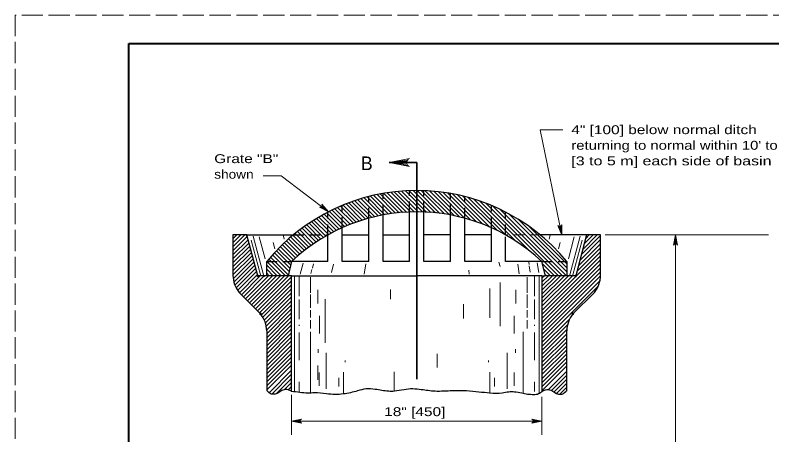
# Model space of a CAD drawing. Extents: x 1302.9 to 1336.9, y 688.5 to 710.5.
# Drawn here: x 1302.88 to 1316.19, y 703.12 to 710.5 of the extents above; entities that cross this region are included whole.
import ezdxf
from ezdxf.enums import TextEntityAlignment as Align

# ---------------------------------------------------------------- set-up
doc = ezdxf.new("R2010")
doc.units = 0
doc.header["$LTSCALE"] = 0.062
doc.header["$PDMODE"] = 32
doc.header["$PDSIZE"] = 0.031
doc.linetypes.add('LONG_DASHED', pattern=[7.5, 6, -1.5])
doc.linetypes.add('MEDIUM_DASHED', pattern=[4.5, 3, -1.5])
doc.layers.add('1', color=7, linetype='Continuous', lineweight=13)

msp = doc.modelspace()

# ---------------------------------------------------------------- linework, layer by layer
at = {"layer": '1', "lineweight": 25}
for p, q in [((1304.8765, 710.00158), (1336.3765, 710.00158)), ((1309.348, 706.16867), (1309.348, 706.98783)), ((1309.81658, 706.16867), (1309.81658, 707.04075)), ((1310.06642, 706.16867), (1310.06642, 707.04075)), ((1310.535, 706.16867), (1310.535, 706.98783)), ((1309.09817, 706.16867), (1309.09817, 706.93033)), ((1310.78483, 706.16867), (1310.78483, 706.93033)), ((1308.62958, 706.16867), (1308.62958, 706.76283)), ((1311.25342, 706.16867), (1311.25342, 706.76283)), ((1306.95333, 706.63708), (1306.70858, 706.63708)), ((1306.70858, 706.63708), (1306.70858, 705.92617)), ((1307.14592, 705.91875), (1306.95333, 706.63708)), ((1306.95333, 706.63708), (1307.76892, 706.63708)), ((1308.37975, 706.16867), (1308.37975, 706.63758)), ((1308.62958, 706.63708), (1309.09817, 706.63708)), ((1309.348, 706.63708), (1309.81658, 706.63708)), ((1310.535, 706.63708), (1310.06642, 706.63708)), ((1311.25342, 706.63708), (1310.78483, 706.63708)), ((1311.50325, 706.16867), (1311.50325, 706.60317)), ((1312.92967, 706.63708), (1312.11408, 706.63708)), ((1313.17442, 706.63708), (1312.92967, 706.63708)), ((1313.17442, 705.92617), (1313.17442, 706.63708)), ((1307.30208, 705.91875), (1307.30208, 706.16867)), ((1308.37975, 706.16867), (1307.73933, 706.16867)), ((1309.09817, 706.16867), (1308.62958, 706.16867)), ((1309.81658, 706.16867), (1309.348, 706.16867)), ((1310.535, 706.16867), (1310.06642, 706.16867)), ((1311.25342, 706.16867), (1310.78483, 706.16867)), ((1312.14367, 706.16867), (1311.50325, 706.16867)), ((1312.58092, 706.16867), (1312.58092, 705.91875)), ((1307.30208, 705.91875), (1307.14592, 705.91875)), ((1307.73933, 705.91875), (1307.67692, 705.91875)), ((1307.73933, 705.91875), (1309.9415, 705.91875)), ((1307.73933, 703.90008), (1307.73933, 705.91875)), ((1312.14367, 705.91875), (1309.9415, 705.91875)), ((1312.14367, 705.91875), (1312.14367, 703.8845)), ((1306.81608, 705.62758), (1307.1945, 705.24925)), ((1312.6885, 705.24925), (1313.06692, 705.62758)), ((1307.30192, 704.95067), (1307.302, 703.9005)), ((1312.58092, 703.88883), (1312.58108, 704.95067))]:
    msp.add_line(p, q, dxfattribs=at)
at = {"layer": '1'}
for p, q in [((1309.77792, 707.95417), (1309.45742, 707.90933)), ((1309.767, 707.932), (1309.45742, 707.90933)), ((1309.76375, 707.90933), (1309.45742, 707.90933)), ((1309.76942, 707.8805), (1309.45742, 707.90933)), ((1309.78167, 707.85975), (1309.45742, 707.90933)), ((1309.82958, 707.04075), (1309.48342, 707.38683)), ((1309.89842, 707.04258), (1309.54642, 707.3945)), ((1309.96892, 707.04275), (1309.60983, 707.40175)), ((1310.04117, 707.04108), (1309.67533, 707.407)), ((1310.11475, 707.03833), (1309.74108, 707.41183)), ((1310.19058, 707.03317), (1309.80875, 707.41492)), ((1310.26842, 707.026), (1309.87733, 707.41692)), ((1310.34808, 707.017), (1309.94725, 707.41767)), ((1310.43017, 707.00558), (1310.01917, 707.4165)), ((1310.51542, 706.991), (1310.09192, 707.41442)), ((1310.60342, 706.97367), (1310.16692, 707.41008)), ((1310.69467, 706.95308), (1310.24367, 707.404)), ((1310.78958, 706.92875), (1310.32192, 707.3965)), ((1310.88925, 706.89992), (1310.40275, 707.38625)), ((1309.20583, 706.95767), (1308.90658, 707.25692)), ((1309.26392, 706.97025), (1308.96075, 707.2735)), ((1309.32225, 706.98267), (1309.01533, 707.2895)), ((1309.382, 706.9935), (1309.07092, 707.30458)), ((1309.44242, 707.00383), (1309.12725, 707.319)), ((1309.50408, 707.01283), (1309.18442, 707.3325)), ((1309.56675, 707.02083), (1309.24233, 707.34525)), ((1309.6305, 707.02775), (1309.30133, 707.35683)), ((1309.69567, 707.03325), (1309.361, 707.36792)), ((1309.76158, 707.03808), (1309.42192, 707.37767)), ((1310.99433, 706.8655), (1310.48608, 707.37367)), ((1311.10633, 706.82417), (1310.5715, 707.35883)), ((1311.22717, 706.774), (1310.65967, 707.3415)), ((1311.35942, 706.7125), (1310.75167, 707.32008)), ((1311.50708, 706.63533), (1310.84742, 707.29508)), ((1311.68542, 706.52775), (1310.94725, 707.26583)), ((1308.24983, 707.12417), (1308.39133, 707.04583)), ((1308.26083, 707.12975), (1308.39133, 707.04583)), ((1308.26892, 707.13783), (1308.39133, 707.04583)), ((1308.27533, 707.15108), (1308.39133, 707.04583)), ((1308.27667, 707.16308), (1308.39133, 707.04583)), ((1308.82617, 706.84258), (1308.54858, 707.12017)), ((1308.87775, 706.86175), (1308.59742, 707.14208)), ((1308.93083, 706.87933), (1308.6475, 707.16258)), ((1308.98383, 706.897), (1308.69767, 707.18308)), ((1309.0385, 706.913), (1308.74917, 707.20242)), ((1309.09317, 706.929), (1308.80067, 707.22133)), ((1309.14942, 706.94333), (1308.85342, 707.23933)), ((1311.93717, 706.34675), (1311.05225, 707.23158)), ((1312.43583, 705.91875), (1311.16333, 707.19125)), ((1312.50658, 705.91875), (1311.282, 707.14308)), ((1308.577, 706.73842), (1308.312, 707.00333)), ((1308.62558, 706.7605), (1308.35808, 707.028)), ((1308.67442, 706.78225), (1308.40475, 707.05208)), ((1308.7245, 706.80292), (1308.45208, 707.07525)), ((1308.77467, 706.8235), (1308.49975, 707.09825)), ((1312.57717, 705.91875), (1311.41067, 707.08517)), ((1312.58092, 705.98575), (1311.55392, 707.01267)), ((1308.34467, 706.61742), (1308.09008, 706.87192)), ((1308.38992, 706.64275), (1308.13358, 706.89917)), ((1308.43583, 706.66758), (1308.177, 706.92633)), ((1308.48217, 706.69183), (1308.22167, 706.95233)), ((1308.52942, 706.71533), (1308.26642, 706.97825)), ((1312.58092, 706.05633), (1311.71908, 706.91817)), ((1308.12767, 706.481), (1307.88225, 706.72642)), ((1308.16958, 706.50975), (1307.92283, 706.75642)), ((1308.21275, 706.53725), (1307.96383, 706.78608)), ((1308.256, 706.56475), (1308.00542, 706.81525)), ((1308.30008, 706.59125), (1308.04767, 706.84367)), ((1312.58092, 706.12708), (1311.92717, 706.78075)), ((1312.44033, 706.78658), (1312.49383, 706.63383)), ((1312.45233, 706.78342), (1312.49383, 706.63383)), ((1312.46375, 706.784), (1312.49383, 706.63383)), ((1312.47733, 706.78958), (1312.49383, 706.63383)), ((1312.48625, 706.79767), (1312.49383, 706.63383)), ((1306.70858, 706.63567), (1306.71, 706.63708)), ((1306.70858, 706.42758), (1306.91817, 706.63708)), ((1306.70858, 706.49817), (1306.8475, 706.63708)), ((1306.70858, 706.56892), (1306.77683, 706.63708)), ((1306.70858, 706.35683), (1306.96083, 706.60917)), ((1306.96025, 706.61133), (1306.93442, 706.63708)), ((1307.24758, 705.93433), (1307.06483, 706.616)), ((1307.27483, 706.21675), (1307.17125, 706.60325)), ((1307.6115, 706.56558), (1307.59233, 706.63708)), ((1307.96442, 706.3615), (1307.72567, 706.60033)), ((1308.00433, 706.39225), (1307.76408, 706.6325)), ((1308.045, 706.42242), (1307.80275, 706.6645)), ((1308.08583, 706.45217), (1307.8425, 706.6955)), ((1312.2715, 706.56558), (1312.29067, 706.63708)), ((1312.60817, 706.21675), (1312.71175, 706.60325)), ((1312.63542, 705.93433), (1312.81817, 706.616)), ((1312.83558, 706.28592), (1313.17442, 706.62475)), ((1312.86142, 706.38242), (1313.11608, 706.63708)), ((1312.88725, 706.479), (1313.04542, 706.63708)), ((1312.91317, 706.57558), (1312.97475, 706.63708)), ((1312.92967, 706.63708), (1313.17442, 706.63708)), ((1313.17442, 706.63567), (1313.173, 706.63708)), ((1316.12867, 706.63708), (1313.25767, 706.63708)), ((1314.46908, 706.475), (1314.49383, 706.63708)), ((1314.4795, 706.48117), (1314.49383, 706.63708)), ((1314.49383, 706.48392), (1314.49383, 706.63708)), ((1314.50517, 706.48233), (1314.49383, 706.63708)), ((1314.51625, 706.47692), (1314.49383, 706.63708)), ((1314.49383, 700.27), (1314.49383, 706.63708)), ((1306.70858, 706.28625), (1306.97583, 706.55333)), ((1306.70858, 706.2155), (1306.99075, 706.49758)), ((1307.19508, 705.93508), (1307.03075, 706.54783)), ((1307.44708, 706.39033), (1307.41675, 706.5035)), ((1307.81, 706.23325), (1307.57742, 706.46583)), ((1307.84808, 706.26592), (1307.6135, 706.50042)), ((1307.88617, 706.2985), (1307.6505, 706.53408)), ((1307.92508, 706.33025), (1307.68783, 706.5675)), ((1312.43592, 706.39033), (1312.46625, 706.5035)), ((1312.688, 705.93508), (1312.85225, 706.54783)), ((1312.78375, 706.09275), (1313.17442, 706.48342)), ((1312.80967, 706.18942), (1313.17442, 706.55408)), ((1306.70858, 706.14492), (1307.00567, 706.44192)), ((1306.70858, 706.07417), (1307.02058, 706.38617)), ((1306.70858, 706.00358), (1307.0355, 706.3305)), ((1307.70992, 706.05075), (1307.43725, 706.32333)), ((1307.72408, 706.10725), (1307.4715, 706.35975)), ((1307.73808, 706.16383), (1307.50633, 706.39558)), ((1307.77308, 706.1995), (1307.54142, 706.43125)), ((1312.14367, 705.31142), (1313.17442, 706.342)), ((1312.75783, 705.99625), (1313.17442, 706.41275)), ((1306.70858, 705.93283), (1307.05042, 706.27475)), ((1306.71292, 705.8665), (1307.06542, 706.219)), ((1307.62975, 705.91875), (1307.33783, 706.21067)), ((1307.68167, 705.93758), (1307.37025, 706.24892)), ((1307.69575, 705.99417), (1307.40358, 706.28625)), ((1312.14367, 705.24075), (1313.17442, 706.27142)), ((1312.14367, 705.17008), (1313.17442, 706.20067)), ((1306.72433, 705.80725), (1307.08033, 706.16325)), ((1306.74158, 705.75392), (1307.09533, 706.1075)), ((1306.76417, 705.70575), (1307.11025, 706.05175)), ((1307.30208, 706.16867), (1307.30208, 705.91875)), ((1307.48842, 705.91875), (1307.30208, 706.10508)), ((1307.55908, 705.91875), (1307.30533, 706.1725)), ((1307.94542, 706.13883), (1307.89017, 705.94708)), ((1308.12483, 706.12967), (1308.105, 706.05483)), ((1308.47717, 706.12058), (1308.43892, 705.97692)), ((1309.04308, 706.13033), (1309.0175, 705.94708)), ((1311.38475, 706.16108), (1311.40583, 706.08192)), ((1311.72025, 706.12433), (1311.7455, 705.95242)), ((1311.91017, 706.15608), (1311.91592, 706.11717)), ((1311.9195, 706.09242), (1311.93542, 705.98417)), ((1312.06075, 706.14608), (1312.086, 705.97417)), ((1312.14367, 705.09942), (1313.17442, 706.13008)), ((1312.14367, 705.02875), (1313.17442, 706.05933)), ((1312.36517, 705.91875), (1312.153, 706.13083)), ((1306.79092, 705.66183), (1307.12517, 705.99608)), ((1306.82175, 705.62192), (1307.14017, 705.94033)), ((1306.857, 705.58667), (1307.18925, 705.91875)), ((1306.89242, 705.55133), (1307.25992, 705.91875)), ((1306.92775, 705.51592), (1307.33058, 705.91875)), ((1306.96308, 705.48058), (1307.40125, 705.91875)), ((1306.99842, 705.44533), (1307.472, 705.91875)), ((1307.03375, 705.41), (1307.54267, 705.91875)), ((1307.06908, 705.37458), (1307.61333, 705.91875)), ((1307.10442, 705.33925), (1307.684, 705.91875)), ((1307.25742, 705.89767), (1307.25175, 705.91875)), ((1307.41775, 705.91875), (1307.30208, 706.0345)), ((1307.34708, 705.91875), (1307.30208, 705.96375)), ((1307.73933, 705.903), (1307.72358, 705.91875)), ((1307.78883, 705.91875), (1307.78883, 703.87517)), ((1307.87325, 705.91875), (1307.87325, 705.56275)), ((1308.09817, 706.02908), (1308.07992, 705.95983)), ((1310.856, 706.01492), (1310.8655, 705.94708)), ((1312.00975, 705.91875), (1312.00975, 705.56275)), ((1312.09417, 705.91875), (1312.09417, 703.86108)), ((1312.14367, 704.95808), (1313.17442, 705.98875)), ((1312.20608, 705.91875), (1312.14367, 705.91875)), ((1312.14367, 705.38208), (1312.68042, 705.91875)), ((1312.14367, 705.45275), (1312.60975, 705.91875)), ((1312.14367, 705.52342), (1312.539, 705.91875)), ((1312.14367, 705.59408), (1312.46842, 705.91875)), ((1312.14367, 705.66475), (1312.39767, 705.91875)), ((1312.14367, 705.73542), (1312.32708, 705.91875)), ((1312.14367, 705.80608), (1312.25633, 705.91875)), ((1312.14367, 705.87675), (1312.18567, 705.91875)), ((1312.14367, 704.88742), (1313.17425, 705.91783)), ((1312.2945, 705.91875), (1312.17658, 706.03667)), ((1312.22383, 705.91875), (1312.20017, 705.94242)), ((1307.13975, 705.304), (1307.73933, 705.9035)), ((1307.17517, 705.26858), (1307.73933, 705.83283)), ((1308.06958, 705.89525), (1308.06958, 705.62117)), ((1311.4085, 705.80017), (1311.4085, 705.03308)), ((1311.88633, 705.89525), (1311.88633, 705.62117)), ((1312.14367, 704.81667), (1313.16567, 705.83858)), ((1307.20817, 705.231), (1307.73933, 705.76208)), ((1307.23642, 705.18858), (1307.73933, 705.6915)), ((1308.20092, 705.43125), (1308.20092, 705.67233)), ((1309.47825, 705.67967), (1309.47825, 705.509)), ((1311.22983, 705.17925), (1311.22983, 705.69792)), ((1311.68208, 705.43125), (1311.68208, 705.67233)), ((1312.14367, 704.746), (1313.13417, 705.7365)), ((1307.26075, 705.14225), (1307.73933, 705.62075)), ((1307.28008, 705.09092), (1307.73933, 705.55017)), ((1308.06958, 705.592), (1308.06958, 705.3545)), ((1311.88633, 705.592), (1311.88633, 705.3545)), ((1307.29392, 705.03408), (1307.73933, 705.47942)), ((1307.3015, 704.97092), (1307.73933, 705.40883)), ((1307.87325, 705.50067), (1307.87325, 705.15367)), ((1308.32858, 705.50792), (1308.32858, 704.74083)), ((1310.76283, 705.16825), (1310.76283, 705.42033)), ((1312.00975, 705.50067), (1312.00975, 705.15367)), ((1307.30192, 704.90067), (1307.73933, 705.33808)), ((1307.30192, 704.83008), (1307.73933, 705.2675)), ((1308.06958, 705.31442), (1308.06958, 705.1865)), ((1311.88633, 705.31442), (1311.88633, 705.1865)), ((1307.30192, 704.75933), (1307.73933, 705.19675)), ((1307.30192, 704.68875), (1307.73933, 705.12617)), ((1308.06958, 705.139), (1308.06958, 704.99292)), ((1308.23008, 704.9015), (1308.23008, 705.21567)), ((1311.65292, 704.9015), (1311.65292, 705.21567)), ((1311.88633, 705.139), (1311.88633, 704.99292)), ((1312.14367, 704.67533), (1312.63325, 705.16492)), ((1307.30192, 704.618), (1307.73933, 705.05542)), ((1307.30192, 704.54742), (1307.73933, 704.98475)), ((1307.87325, 705.05858), (1307.87325, 705.04033)), ((1312.00975, 705.05858), (1312.00975, 705.04033)), ((1312.14367, 704.60475), (1312.59317, 705.05417)), ((1307.302, 704.47667), (1307.73933, 704.91408)), ((1307.87325, 704.91983), (1307.87325, 704.434)), ((1308.06958, 704.93075), (1308.06958, 703.94083)), ((1311.81342, 704.93075), (1311.81342, 703.94083)), ((1312.00975, 704.91983), (1312.00975, 704.434)), ((1312.14367, 704.534), (1312.58208, 704.97242)), ((1312.14367, 704.46333), (1312.58108, 704.90075)), ((1307.302, 704.40608), (1307.73933, 704.84342)), ((1307.302, 704.33542), (1307.73933, 704.77275)), ((1312.14367, 704.39267), (1312.58108, 704.83008)), ((1312.14367, 704.322), (1312.58108, 704.75942)), ((1307.302, 704.26475), (1307.73933, 704.70208)), ((1307.302, 704.19408), (1307.73933, 704.63142)), ((1308.20458, 704.5655), (1308.20458, 704.63125)), ((1311.67842, 704.5655), (1311.67842, 704.63125)), ((1312.14367, 704.25133), (1312.58108, 704.68875)), ((1312.14367, 704.18067), (1312.58108, 704.618)), ((1307.302, 704.12342), (1307.73933, 704.56075)), ((1307.302, 704.05275), (1307.73933, 704.49008)), ((1308.3505, 704.56183), (1308.3505, 703.9335)), ((1310.30325, 704.30608), (1310.30325, 704.54717)), ((1311.5325, 704.56183), (1311.5325, 703.9335)), ((1312.14367, 704.11), (1312.58108, 704.54742)), ((1312.14367, 704.03933), (1312.581, 704.47667)), ((1307.302, 703.98208), (1307.73933, 704.41942)), ((1307.302, 703.91142), (1307.73933, 704.34875)), ((1308.20092, 704.08692), (1308.20092, 704.339)), ((1308.68242, 704.42667), (1308.68242, 704.39742)), ((1311.20058, 704.42667), (1311.20058, 704.39742)), ((1312.14367, 703.96867), (1312.581, 704.406)), ((1312.14367, 703.898), (1312.581, 704.33533)), ((1307.34833, 703.86608), (1307.73933, 704.25708)), ((1307.38917, 703.83625), (1307.73933, 704.18642)), ((1308.65317, 704.22208), (1308.65317, 703.85175)), ((1309.54325, 704.22933), (1309.54325, 703.8845)), ((1311.22983, 704.22208), (1311.22983, 703.85175)), ((1312.25625, 703.91892), (1312.581, 704.24367)), ((1307.46608, 703.8425), (1307.73933, 704.11575)), ((1307.87325, 704.05633), (1307.87325, 703.88567)), ((1308.06958, 704.12217), (1308.06958, 703.86275)), ((1308.573, 703.97008), (1308.573, 704.1235)), ((1311.31, 703.97008), (1311.31, 704.1235)), ((1311.81342, 704.12217), (1311.81342, 703.86275)), ((1312.00975, 704.05633), (1312.00975, 703.88567)), ((1312.31142, 703.90333), (1312.581, 704.17292)), ((1312.35225, 703.87358), (1312.581, 704.10233)), ((1307.61075, 703.91642), (1307.73933, 704.045)), ((1307.67842, 703.91342), (1307.73933, 703.97442)), ((1312.3995, 703.85017), (1312.581, 704.03158)), ((1312.45183, 703.83175), (1312.581, 703.96092)), ((1307.72758, 703.89183), (1307.73933, 703.90367)), ((1307.73933, 703.82842), (1307.73933, 703.12417)), ((1312.14367, 703.791), (1312.14367, 703.12417)), ((1307.89958, 703.38717), (1307.73933, 703.36475)), ((1307.89417, 703.37608), (1307.73933, 703.36475)), ((1307.8925, 703.36475), (1307.73933, 703.36475)), ((1307.89533, 703.35033), (1307.73933, 703.36475)), ((1307.9015, 703.34), (1307.73933, 703.36475)), ((1311.9815, 703.34), (1312.14367, 703.36475)), ((1311.98342, 703.38717), (1312.14367, 703.36475)), ((1311.98767, 703.35033), (1312.14367, 703.36475)), ((1311.98883, 703.37608), (1312.14367, 703.36475)), ((1311.9905, 703.36475), (1312.14367, 703.36475))]:
    msp.add_line(p, q, dxfattribs=at)
at = {"layer": '1', "lineweight": 35}
for p, q in [((1309.9415, 707.90933), (1309.45742, 707.90933)), ((1309.9415, 707.00683), (1309.9415, 707.90933)), ((1309.9415, 704.10408), (1309.9415, 707.01467))]:
    msp.add_line(p, q, dxfattribs=at)
at = {"layer": '1', "linetype": 'MEDIUM_DASHED', "lineweight": 25}
for p, q in [((1309.81658, 707.04075), (1309.81658, 707.41567)), ((1310.06642, 707.04075), (1310.06642, 707.41567)), ((1309.09817, 706.93033), (1309.09817, 707.31208)), ((1309.348, 706.98783), (1309.348, 707.36592)), ((1310.535, 706.98783), (1310.535, 707.36592)), ((1310.78483, 706.93033), (1310.78483, 707.31208)), ((1308.62958, 706.76283), (1308.62958, 707.15575)), ((1311.25342, 706.76283), (1311.25342, 707.15575)), ((1308.37975, 706.63758), (1308.37975, 707.03967)), ((1311.50325, 706.63758), (1311.50325, 707.03967)), ((1307.76892, 706.63708), (1308.37975, 706.63708)), ((1307.30208, 706.16867), (1307.73933, 706.16867)), ((1312.14367, 706.16867), (1312.58092, 706.16867))]:
    msp.add_line(p, q, dxfattribs=at)
at = {"layer": '1', "linetype": 'MEDIUM_DASHED'}
msp.add_line((1312.11408, 706.63708), (1311.50325, 706.63708), dxfattribs=at)
at = {"layer": '1', "linetype": 'LONG_DASHED'}
msp.add_lwpolyline([(1302.8765, 688.50158), (1336.8765, 688.50158), (1336.8765, 710.50158), (1302.8765, 710.50158)], close=True, dxfattribs=at)
at = {"layer": '1', "lineweight": 25}
for points in [[(1336.3765, 689.00158), (1304.8765, 689.00158), (1304.8765, 710.00158)], [(1312.92967, 706.63708), (1312.73708, 705.91875), (1312.58092, 705.91875)], [(1307.73933, 706.16867), (1307.67692, 705.91875), (1307.30208, 705.91875)], [(1312.58092, 705.91875), (1312.20608, 705.91875), (1312.14367, 706.16867)]]:
    msp.add_lwpolyline(points, dxfattribs=at)
at = {"layer": '1', "lineweight": 40}
msp.add_lwpolyline([(1304.8765, 710.00158), (1336.3765, 710.00158), (1336.3765, 689.00158), (1304.8765, 689.00158)], close=True, dxfattribs=at)
msp.add_lwpolyline([(1304.8765, 710.00158), (1336.3765, 710.00158), (1336.3765, 689.00158), (1304.8765, 689.00158)], close=True, dxfattribs=at)
at = {"layer": '1'}
for points in [[(1312.49383, 706.63383), (1312.11517, 708.48425), (1312.51375, 708.48425)], [(1309.81142, 707.8385), (1309.45742, 707.90933), (1309.81142, 707.98008)], [(1308.39133, 707.04583), (1307.55625, 707.67583), (1307.23742, 707.67583)], [(1308.27117, 707.1805), (1308.39133, 707.04583), (1308.22858, 707.12392)], [(1312.49375, 706.81433), (1312.49383, 706.63383), (1312.42433, 706.80042)], [(1314.4585, 706.46008), (1314.49383, 706.63708), (1314.52925, 706.46008)], [(1308.2265, 703.98333), (1308.2265, 704.06367), (1308.2265, 704.22075)], [(1311.6565, 703.98333), (1311.6565, 704.06367), (1311.6565, 704.22075)], [(1307.91633, 703.32933), (1307.73933, 703.36475), (1307.91633, 703.40017)], [(1311.96667, 703.32933), (1312.14367, 703.36475), (1311.96667, 703.40017)], [(1312.14367, 703.36475), (1310.27467, 703.36475), (1307.73933, 703.36475)]]:
    msp.add_lwpolyline(points, dxfattribs=at)
for centre, radius, start, end in [((1309.83998, 707.90938), 0.0764, 112.08782, 247.91395), ((1308.23843, 707.16073), 0.0382, 255.15895, 30.98508), ((1312.45621, 706.82139), 0.0382, 213.42376, 349.24989), ((1314.4939, 706.44583), 0.0382, 22.08782, 157.91395), ((1307.93066, 703.36478), 0.0382, 112.08782, 247.91395), ((1311.95233, 703.36478), 0.0382, 292.08605, 67.91218)]:
    msp.add_arc(centre, radius, start, end, dxfattribs=at)
at = {"layer": '1', "lineweight": 25}
for centre, major_axis, start_param, end_param in [((1309.9415, 704.00564), (3.41264, 0), 0.68656885, 2.45502381), ((1309.9415, 703.8338), (3.20967, 0), 0.8146925, 2.32690016), ((1307.17713, 705.9262), (0.46853, 0), 3.14159265, 3.83256967), ((1312.70587, 705.9262), (-0.46853, 0), 2.45061564, 3.14159265), ((1306.83338, 704.95067), (-0.46853, 0), 3.14159265, 3.83256967), ((1313.04962, 704.95067), (0.46853, 0), 2.45061564, 3.14159265)]:
    msp.add_ellipse(centre, major_axis=major_axis, ratio=0.999895, start_param=start_param, end_param=end_param, dxfattribs=at)
for points in [[(1307.73933, 703.8855), (1307.67717, 703.91392), (1307.58392, 703.909), (1307.51525, 703.86483), (1307.38275, 703.84025), (1307.30208, 703.9005)], [(1312.14367, 703.8855), (1312.08533, 703.84142), (1311.99758, 703.82792), (1311.88967, 703.83467), (1311.7885, 703.85492), (1311.66025, 703.87508), (1311.55908, 703.87508), (1311.44442, 703.85492), (1311.2285, 703.85492), (1311.03283, 703.87508), (1310.817, 703.89542), (1310.56733, 703.89542), (1310.26375, 703.88867), (1310.02092, 703.91567), (1309.87242, 703.92917), (1309.71725, 703.91567), (1309.54867, 703.88867), (1309.4475, 703.88867), (1309.21133, 703.92242), (1309.04942, 703.92917), (1308.901, 703.89542), (1308.65133, 703.84142), (1308.3545, 703.84142), (1308.14542, 703.86167), (1308.024, 703.85492), (1307.88233, 703.86842), (1307.73933, 703.8855)], [(1312.14367, 703.8855), (1312.20583, 703.91392), (1312.29908, 703.909), (1312.36775, 703.86483), (1312.50025, 703.84025), (1312.58092, 703.9005)]]:
    msp.add_spline(points, degree=3, dxfattribs=at)
at = {"layer": '1'}
for p in [(1307.14592, 705.91875), (1312.73708, 705.91875), (1307.1945, 705.24925), (1312.6885, 705.24925)]:
    msp.add_point(p, dxfattribs=at)

# ---------------------------------------------------------------- texts
for s, height, width, p in [('4" [100] below normal ditch', 0.156, 1.3, (1312.66033, 708.40917)), ("returning to normal within 10' to 15'", 0.156, 1.25, (1312.66033, 708.13517)), ('Grate "B"', 0.156, 1.3, (1306.37842, 707.89992)), ('B', 0.24, 0.95, (1308.96117, 707.7765)), ('[3 to 5 m] each side of basin', 0.156, 1.35, (1312.66033, 707.86117)), ('shown', 0.156, 1.15, (1306.37842, 707.62592))]:
    msp.add_text(s, height=height, dxfattribs=dict(at, width=width)).set_placement(p)
at = {"layer": '1', "width": 1.3}
msp.add_text('18" [450]', height=0.156, dxfattribs=at).set_placement((1309.90704, 703.45167), align=Align.CENTER)

doc.saveas('drawing.dxf')
